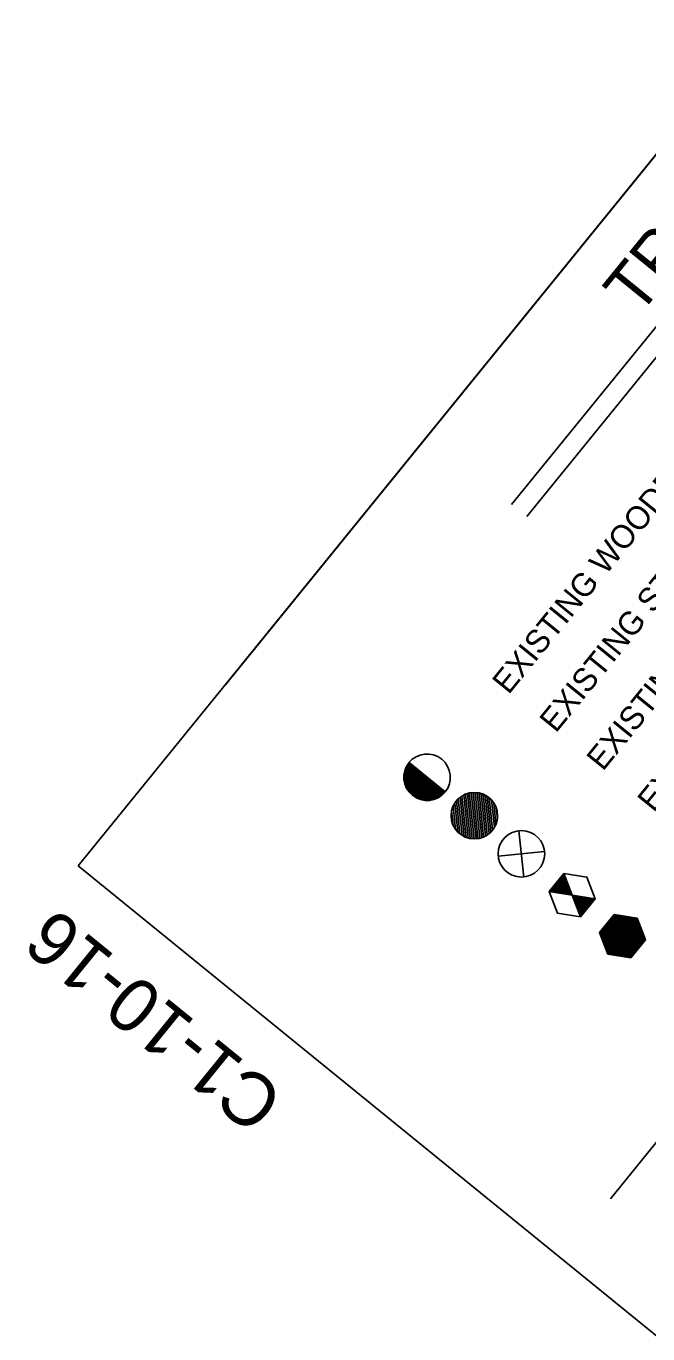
# Model space of a CAD drawing. Extents: x 592613 to 600223, y 4837996 to 4840103.
# Drawn here: x 592901.33 to 592912.92, y 4839262.21 to 4839286.58 of the extents above; entities that cross this region are included whole.
import ezdxf

# ---------------------------------------------------------------- set-up
doc = ezdxf.new("R2010")
doc.units = 0
for name, color, linetype in [('ENG_BORDER', 7, 'Continuous'), ('ENG_TX_BORDER', 7, 'Continuous'), ('TCS_100mm-EXIST', 7, 'Continuous'), ('TCS_ELEC-CHAMBER-EXIST', 7, 'Continuous'), ('TCS_LEGEND', 7, 'Continuous'), ('TCS_POLE-EXIST', 7, 'Continuous')]:
    doc.layers.add(name, color=color, linetype=linetype)

msp = doc.modelspace()

# ---------------------------------------------------------------- linework, layer by layer
at = {"layer": 'ENG_BORDER'}
for points in [[(593027.682, 4839425.246), (592902.303, 4839270.934)], [(592902.303, 4839270.934), (593006.685, 4839186.123)]]:
    msp.add_lwpolyline(points, dxfattribs=at)
at = {"layer": 'TCS_100mm-EXIST'}
msp.add_line((592912.225, 4839264.73), (592918.531, 4839272.491), dxfattribs=at)
at = {"layer": 'TCS_ELEC-CHAMBER-EXIST'}
for p, q in [((592911.185, 4839270.44), (592911.172, 4839270.562)), ((592911.199, 4839270.438), (592911.185, 4839270.578)), ((592911.214, 4839270.435), (592911.198, 4839270.594)), ((592911.229, 4839270.433), (592911.211, 4839270.61)), ((592911.244, 4839270.431), (592911.223, 4839270.626)), ((592911.258, 4839270.428), (592911.236, 4839270.641)), ((592911.273, 4839270.426), (592911.249, 4839270.657)), ((592911.288, 4839270.423), (592911.262, 4839270.673)), ((592911.303, 4839270.421), (592911.275, 4839270.689)), ((592911.318, 4839270.419), (592911.288, 4839270.705)), ((592911.332, 4839270.416), (592911.301, 4839270.721)), ((592911.347, 4839270.414), (592911.314, 4839270.737)), ((592911.362, 4839270.412), (592911.327, 4839270.752)), ((592911.377, 4839270.409), (592911.34, 4839270.768)), ((592911.391, 4839270.407), (592911.352, 4839270.784)), ((592911.406, 4839270.405), (592911.369, 4839270.768)), ((592911.421, 4839270.402), (592911.389, 4839270.715)), ((592911.436, 4839270.4), (592911.409, 4839270.663)), ((592911.451, 4839270.397), (592911.428, 4839270.611)), ((592911.096, 4839270.454), (592911.095, 4839270.467)), ((592911.111, 4839270.452), (592911.107, 4839270.483)), ((592911.125, 4839270.45), (592911.12, 4839270.499)), ((592911.14, 4839270.447), (592911.133, 4839270.514)), ((592911.155, 4839270.445), (592911.146, 4839270.53)), ((592911.17, 4839270.442), (592911.159, 4839270.546)), ((592911.465, 4839270.395), (592911.448, 4839270.559)), ((592911.48, 4839270.393), (592911.468, 4839270.507)), ((592911.495, 4839270.39), (592911.488, 4839270.454)), ((592911.51, 4839270.388), (592911.508, 4839270.402)), ((592911.532, 4839270.34), (592911.527, 4839270.385)), ((592911.552, 4839270.288), (592911.542, 4839270.383)), ((592911.572, 4839270.236), (592911.557, 4839270.38)), ((592911.592, 4839270.183), (592911.572, 4839270.378)), ((592911.612, 4839270.131), (592911.586, 4839270.376)), ((592911.632, 4839270.079), (592911.601, 4839270.373)), ((592911.652, 4839270.027), (592911.616, 4839270.371)), ((592911.671, 4839269.984), (592911.631, 4839270.369)), ((592911.683, 4839270), (592911.646, 4839270.366)), ((592911.696, 4839270.016), (592911.66, 4839270.364)), ((592911.709, 4839270.032), (592911.675, 4839270.362)), ((592911.722, 4839270.048), (592911.69, 4839270.359)), ((592911.735, 4839270.064), (592911.705, 4839270.357)), ((592911.748, 4839270.08), (592911.72, 4839270.354)), ((592911.761, 4839270.096), (592911.734, 4839270.352)), ((592911.774, 4839270.111), (592911.749, 4839270.35)), ((592911.787, 4839270.127), (592911.764, 4839270.347)), ((592911.8, 4839270.143), (592911.779, 4839270.345)), ((592911.812, 4839270.159), (592911.793, 4839270.343)), ((592911.825, 4839270.175), (592911.808, 4839270.34)), ((592911.838, 4839270.191), (592911.823, 4839270.338)), ((592911.851, 4839270.207), (592911.838, 4839270.336)), ((592911.864, 4839270.222), (592911.853, 4839270.333)), ((592911.877, 4839270.238), (592911.867, 4839270.331)), ((592911.89, 4839270.254), (592911.882, 4839270.328)), ((592911.903, 4839270.27), (592911.897, 4839270.326)), ((592911.916, 4839270.286), (592911.912, 4839270.324)), ((592911.928, 4839270.302), (592911.926, 4839270.321)), ((592911.941, 4839270.318), (592911.941, 4839270.319)), ((592912.024, 4839269.694), (592912.297, 4839270.03)), ((592912.297, 4839270.03), (592912.024, 4839269.694)), ((592912.297, 4839270.03), (592912.024, 4839269.694)), ((592912.297, 4839270.03), (592912.024, 4839269.694)), ((592912.192, 4839269.286), (592912.135, 4839269.831)), ((592912.206, 4839269.284), (592912.148, 4839269.847)), ((592912.221, 4839269.282), (592912.161, 4839269.863)), ((592912.236, 4839269.279), (592912.174, 4839269.879)), ((592912.251, 4839269.277), (592912.187, 4839269.895)), ((592912.266, 4839269.275), (592912.2, 4839269.91)), ((592912.28, 4839269.272), (592912.213, 4839269.926)), ((592912.295, 4839269.27), (592912.226, 4839269.942)), ((592912.31, 4839269.268), (592912.238, 4839269.958)), ((592912.325, 4839269.265), (592912.251, 4839269.974)), ((592912.339, 4839269.263), (592912.264, 4839269.99)), ((592912.354, 4839269.26), (592912.277, 4839270.006)), ((592912.369, 4839269.258), (592912.29, 4839270.022)), ((592912.297, 4839270.03), (592912.725, 4839269.962)), ((592912.725, 4839269.962), (592912.297, 4839270.03)), ((592912.725, 4839269.962), (592912.297, 4839270.03)), ((592912.725, 4839269.962), (592912.297, 4839270.03)), ((592912.384, 4839269.256), (592912.304, 4839270.029)), ((592912.399, 4839269.253), (592912.318, 4839270.027)), ((592912.413, 4839269.251), (592912.333, 4839270.025)), ((592912.428, 4839269.249), (592912.348, 4839270.022)), ((592912.443, 4839269.246), (592912.363, 4839270.02)), ((592912.458, 4839269.244), (592912.378, 4839270.018)), ((592912.472, 4839269.242), (592912.392, 4839270.015)), ((592912.487, 4839269.239), (592912.407, 4839270.013)), ((592912.502, 4839269.237), (592912.422, 4839270.01)), ((592912.517, 4839269.234), (592912.437, 4839270.008)), ((592912.532, 4839269.232), (592912.452, 4839270.006)), ((592912.546, 4839269.23), (592912.466, 4839270.003)), ((592912.561, 4839269.227), (592912.481, 4839270.001)), ((592912.576, 4839269.225), (592912.496, 4839269.999)), ((592912.591, 4839269.223), (592912.511, 4839269.996)), ((592912.605, 4839269.22), (592912.525, 4839269.994)), ((592912.619, 4839269.235), (592912.54, 4839269.991)), ((592912.631, 4839269.25), (592912.555, 4839269.989)), ((592912.644, 4839269.266), (592912.57, 4839269.987)), ((592912.657, 4839269.282), (592912.585, 4839269.984)), ((592912.67, 4839269.298), (592912.599, 4839269.982)), ((592912.683, 4839269.314), (592912.614, 4839269.98)), ((592912.696, 4839269.33), (592912.629, 4839269.977)), ((592912.709, 4839269.346), (592912.644, 4839269.975)), ((592912.722, 4839269.362), (592912.658, 4839269.973)), ((592912.735, 4839269.377), (592912.673, 4839269.97)), ((592912.747, 4839269.393), (592912.688, 4839269.968)), ((592912.76, 4839269.409), (592912.703, 4839269.965)), ((592912.773, 4839269.425), (592912.718, 4839269.963)), ((592912.725, 4839269.962), (592912.88, 4839269.557)), ((592912.88, 4839269.557), (592912.725, 4839269.962)), ((592912.88, 4839269.557), (592912.725, 4839269.962)), ((592912.88, 4839269.557), (592912.725, 4839269.962)), ((592912.786, 4839269.441), (592912.735, 4839269.937)), ((592912.799, 4839269.457), (592912.755, 4839269.885)), ((592912.812, 4839269.473), (592912.775, 4839269.833)), ((592912.024, 4839269.694), (592912.178, 4839269.289)), ((592912.024, 4839269.694), (592912.178, 4839269.289)), ((592912.024, 4839269.694), (592912.178, 4839269.289)), ((592912.024, 4839269.694), (592912.178, 4839269.289)), ((592912.037, 4839269.659), (592912.032, 4839269.704)), ((592912.057, 4839269.607), (592912.045, 4839269.72)), ((592912.077, 4839269.555), (592912.058, 4839269.736)), ((592912.097, 4839269.503), (592912.071, 4839269.752)), ((592912.116, 4839269.451), (592912.084, 4839269.768)), ((592912.136, 4839269.399), (592912.097, 4839269.784)), ((592912.156, 4839269.346), (592912.109, 4839269.799)), ((592912.176, 4839269.294), (592912.122, 4839269.815)), ((592912.825, 4839269.488), (592912.795, 4839269.781)), ((592912.838, 4839269.504), (592912.814, 4839269.729)), ((592912.851, 4839269.52), (592912.834, 4839269.677)), ((592912.863, 4839269.536), (592912.854, 4839269.624)), ((592912.607, 4839269.22), (592912.88, 4839269.557)), ((592912.607, 4839269.22), (592912.88, 4839269.557)), ((592912.607, 4839269.22), (592912.88, 4839269.557)), ((592912.607, 4839269.22), (592912.88, 4839269.557)), ((592912.876, 4839269.552), (592912.874, 4839269.572)), ((592912.178, 4839269.289), (592912.607, 4839269.22)), ((592912.178, 4839269.289), (592912.607, 4839269.22)), ((592912.178, 4839269.289), (592912.607, 4839269.22)), ((592912.178, 4839269.289), (592912.607, 4839269.22))]:
    msp.add_line(p, q, dxfattribs=at)
for points in [[(592911.359, 4839270.793), (592911.514, 4839270.387), (592911.086, 4839270.456)], [(592911.669, 4839269.982), (592911.514, 4839270.387), (592911.942, 4839270.319)]]:
    msp.add_lwpolyline(points, close=True, dxfattribs=at)
for points in [[(592911.942, 4839270.319), (592911.787, 4839270.724), (592911.359, 4839270.793)], [(592911.086, 4839270.456), (592911.24, 4839270.051), (592911.669, 4839269.982)]]:
    msp.add_lwpolyline(points, dxfattribs=at)
at = {"layer": 'TCS_LEGEND'}
for p, q in [((592910.384, 4839277.672), (592924.901, 4839295.539)), ((592910.666, 4839277.443), (592925.183, 4839295.31))]:
    msp.add_line(p, q, dxfattribs=at)
msp.add_lwpolyline([(592905.041, 4839274.303), (592927.104, 4839301.458)], dxfattribs=at)
at = {"layer": 'TCS_POLE-EXIST'}
for p, q in [((592908.451, 4839272.341), (592908.408, 4839272.755)), ((592908.468, 4839272.318), (592908.42, 4839272.781)), ((592908.485, 4839272.298), (592908.432, 4839272.803)), ((592908.501, 4839272.281), (592908.445, 4839272.824)), ((592908.517, 4839272.266), (592908.457, 4839272.842)), ((592908.533, 4839272.252), (592908.47, 4839272.859)), ((592908.472, 4839272.861), (592908.472, 4839272.86)), ((592908.472, 4839272.86), (592909.145, 4839272.313)), ((592908.549, 4839272.24), (592908.486, 4839272.849)), ((592908.564, 4839272.228), (592908.502, 4839272.836)), ((592908.58, 4839272.218), (592908.517, 4839272.823)), ((592908.596, 4839272.209), (592908.533, 4839272.81)), ((592908.611, 4839272.201), (592908.549, 4839272.797)), ((592908.626, 4839272.193), (592908.565, 4839272.785)), ((592908.641, 4839272.187), (592908.581, 4839272.772)), ((592908.657, 4839272.181), (592908.597, 4839272.759)), ((592908.396, 4839272.453), (592908.377, 4839272.634)), ((592908.416, 4839272.403), (592908.386, 4839272.687)), ((592908.434, 4839272.369), (592908.397, 4839272.724)), ((592908.672, 4839272.175), (592908.613, 4839272.746)), ((592908.687, 4839272.171), (592908.629, 4839272.733)), ((592908.702, 4839272.167), (592908.644, 4839272.72)), ((592908.717, 4839272.163), (592908.66, 4839272.707)), ((592908.731, 4839272.16), (592908.676, 4839272.694)), ((592908.746, 4839272.158), (592908.692, 4839272.681)), ((592908.761, 4839272.156), (592908.708, 4839272.668)), ((592908.776, 4839272.155), (592908.724, 4839272.656)), ((592908.79, 4839272.154), (592908.74, 4839272.643)), ((592908.805, 4839272.153), (592908.756, 4839272.63)), ((592908.819, 4839272.154), (592908.771, 4839272.617)), ((592908.834, 4839272.154), (592908.787, 4839272.604)), ((592908.848, 4839272.155), (592908.803, 4839272.591)), ((592908.863, 4839272.157), (592908.819, 4839272.578)), ((592908.877, 4839272.159), (592908.835, 4839272.565)), ((592908.891, 4839272.161), (592908.851, 4839272.552)), ((592908.905, 4839272.164), (592908.867, 4839272.54)), ((592908.92, 4839272.168), (592908.882, 4839272.527)), ((592908.934, 4839272.172), (592908.898, 4839272.514)), ((592908.948, 4839272.176), (592908.914, 4839272.501)), ((592908.962, 4839272.181), (592908.93, 4839272.488)), ((592908.976, 4839272.187), (592908.946, 4839272.475)), ((592908.99, 4839272.193), (592908.962, 4839272.462)), ((592909.004, 4839272.2), (592908.978, 4839272.449)), ((592909.017, 4839272.207), (592908.994, 4839272.436)), ((592909.031, 4839272.215), (592909.009, 4839272.424)), ((592909.045, 4839272.223), (592909.025, 4839272.411)), ((592909.058, 4839272.233), (592909.041, 4839272.398)), ((592909.072, 4839272.243), (592909.057, 4839272.385)), ((592909.085, 4839272.253), (592909.073, 4839272.372)), ((592909.099, 4839272.265), (592909.089, 4839272.359)), ((592909.112, 4839272.277), (592909.105, 4839272.346)), ((592909.125, 4839272.291), (592909.121, 4839272.333)), ((592909.138, 4839272.305), (592909.136, 4839272.32)), ((592909.144, 4839272.313), (592909.144, 4839272.314)), ((592909.611, 4839271.444), (592909.525, 4839272.272)), ((592909.648, 4839271.438), (592909.56, 4839272.284)), ((592909.684, 4839271.436), (592909.595, 4839272.294)), ((592909.72, 4839271.438), (592909.631, 4839272.3)), ((592909.756, 4839271.442), (592909.667, 4839272.303)), ((592909.792, 4839271.449), (592909.703, 4839272.304)), ((592909.827, 4839271.459), (592909.74, 4839272.301)), ((592909.862, 4839271.472), (592909.777, 4839272.295)), ((592909.897, 4839271.489), (592909.814, 4839272.285)), ((592909.931, 4839271.51), (592909.852, 4839272.272)), ((592909.339, 4839271.614), (592909.294, 4839272.049)), ((592909.38, 4839271.566), (592909.324, 4839272.105)), ((592909.42, 4839271.53), (592909.356, 4839272.148)), ((592909.459, 4839271.502), (592909.389, 4839272.183)), ((592909.498, 4839271.481), (592909.422, 4839272.212)), ((592909.536, 4839271.464), (592909.456, 4839272.236)), ((592909.573, 4839271.452), (592909.49, 4839272.256)), ((592909.965, 4839271.535), (592909.89, 4839272.254)), ((592909.998, 4839271.566), (592909.929, 4839272.231)), ((592910.03, 4839271.603), (592909.968, 4839272.202)), ((592910.062, 4839271.649), (592910.009, 4839272.163)), ((592910.092, 4839271.71), (592910.05, 4839272.11)), ((592909.295, 4839271.69), (592909.266, 4839271.966)), ((592910.118, 4839271.807), (592910.096, 4839272.019)), ((592910.61, 4839270.726), (592910.521, 4839271.589)), ((592910.134, 4839271.113), (592910.997, 4839271.202))]:
    msp.add_line(p, q, dxfattribs=at)
for centre in [(592909.689, 4839271.87), (592910.566, 4839271.158)]:
    msp.add_circle(centre, 0.434, dxfattribs=at)
for centre, start, end in [((592908.807, 4839272.585), 320.9061, 140.9061), ((592908.808, 4839272.587), 140.9061, 320.9061)]:
    msp.add_arc(centre, 0.434, start, end, dxfattribs=at)

# ---------------------------------------------------------------- texts
at = {"layer": 'ENG_TX_BORDER'}
msp.add_text('C1-10-16', height=1, rotation=140.906, dxfattribs=at).set_placement((592906.192, 4839266.662))
at = {"layer": 'TCS_LEGEND'}
for s, height, p in [('TRAFFIC SYMBOLS LEGEND', 0.90363, (592912.749, 4839281.158)), ('EXISTING ELECTRICAL CHAMBER (300mm)', 0.43374, (592913.033, 4839271.914)), ('EXISTING WOODEN POLE', 0.43374, (592910.327, 4839274.112)), ('EXISTING CONCRETE POLE', 0.43374, (592912.085, 4839272.684)), ('EXISTING STEEL POLE', 0.43374, (592911.208, 4839273.396))]:
    msp.add_text(s, height=height, rotation=50.9061, dxfattribs=at).set_placement(p)

doc.saveas('drawing.dxf')
